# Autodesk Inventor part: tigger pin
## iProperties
Created: 2006-04
Part Number: tigger pin
Document SubType Name: Modeling
Designer: Калинин
Author: Калинин
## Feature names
1. Сдвиг1
2. Выдавливание1 [Extrusion]
3. Выдавливание2 [Extrusion]
4. Выдавливание3 [Extrusion]
5. Выдавливание4 [Extrusion]
6. Фаска1 [Chamfer]
